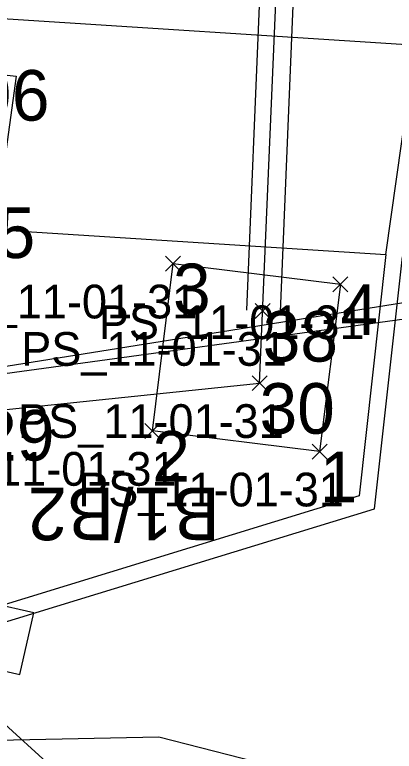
# Model space of a CAD drawing. Extents: x -728800 to -728100, y -1073200 to -1072700.
# Drawn here: x -728498.52 to -728494.02, y -1073052.38 to -1073043.64 of the extents above; entities that cross this region are included whole.
import ezdxf

# ---------------------------------------------------------------- set-up
doc = ezdxf.new("R2010")
doc.units = 0
for name, color, linetype in [('A1_OBVOD Spravy železnic', 7, 'Continuous'), ('A2_OBVOD STAVBY', 7, 'Continuous'), ('B1_body_poloha', 7, 'Continuous'), ('B2_body_číslo', 7, 'Continuous'), ('B3_body_popiska', 7, 'Continuous'), ('B4_Bodové pole', 7, 'Continuous'), ('B6_JŽM', 7, 'Continuous'), ('KOS_kabelová trasa', 7, 'Continuous'), ('KOS_nové prvky PZZ', 7, 'Continuous'), ('KTA_členění PS a SO', 7, 'Continuous'), ('ZA_02_Dočasný_do_1_roku', 7, 'Continuous')]:
    doc.layers.add(name, color=color, linetype=linetype)

msp = doc.modelspace()

# ---------------------------------------------------------------- linework, layer by layer
at = {"layer": 'A1_OBVOD Spravy železnic'}
msp.add_lwpolyline([(-728503.24, -1073052.34), (-728496.81, -1073052.21), (-728491.97, -1073053.44), (-728477.97, -1073053.19), (-728470.97, -1073054.08), (-728434.43, -1073049.27), (-728361.73, -1073039.5), (-728349.1656, -1073038.9844)], dxfattribs=at)
at = {"layer": 'A2_OBVOD STAVBY'}
msp.add_lwpolyline([(-728503.756, -1073049.5471), (-728504.3576, -1073053.4259), (-728503.4626, -1073053.5721), (-728499.6278, -1073054.1986), (-728499.1285, -1073052.28), (-728499.1998, -1073051.021), (-728494.2501, -1073049.503), (-728493.9181, -1073046.5148)], dxfattribs=at)
at = {"layer": 'B1_body_poloha'}
for p, q in [((-728496.7304, -1073046.5076), (-728496.5536, -1073046.6844)), ((-728496.7304, -1073046.6844), (-728496.5536, -1073046.5076)), ((-728494.7454, -1073046.7536), (-728494.5686, -1073046.9304)), ((-728494.7454, -1073046.9304), (-728494.5686, -1073046.7536)), ((-728495.6664, -1073047.0696), (-728495.4896, -1073047.2464)), ((-728495.6664, -1073047.2464), (-728495.4896, -1073047.0696)), ((-728495.7034, -1073047.9256), (-728495.5266, -1073048.1024)), ((-728495.7034, -1073048.1024), (-728495.5266, -1073047.9256)), ((-728496.9754, -1073048.4926), (-728496.7986, -1073048.6694)), ((-728496.9754, -1073048.6694), (-728496.7986, -1073048.4926)), ((-728494.9904, -1073048.7376), (-728494.8136, -1073048.9144)), ((-728494.9904, -1073048.9144), (-728494.8136, -1073048.7376))]:
    msp.add_line(p, q, dxfattribs=at)
at = {"layer": 'B2_body_číslo'}
for p, q in [((-728496.642, -1073046.596), (-728496.642, -1073046.596)), ((-728494.657, -1073046.842), (-728494.657, -1073046.842)), ((-728495.578, -1073047.158), (-728495.578, -1073047.158)), ((-728495.615, -1073048.014), (-728495.615, -1073048.014)), ((-728496.887, -1073048.581), (-728496.887, -1073048.581)), ((-728494.902, -1073048.826), (-728494.902, -1073048.826))]:
    msp.add_line(p, q, dxfattribs=at)
at = {"layer": 'B4_Bodové pole'}
msp.add_line((-728502.086, -1073048.369), (-728399.517, -1073034.362), dxfattribs=at)
msp.add_lwpolyline([(-728665.963, -1072915.444), (-728594.709, -1073015.734), (-728502.086, -1073048.369), (-728347.458, -1073023.537)], dxfattribs=at)
at = {"layer": 'B6_JŽM'}
for points in [[(-728300.8085, -1073024.3545), (-728320.8, -1073026.914), (-728374.008, -1073033.722), (-728429.095, -1073040.747), (-728461.932, -1073044.273), (-728481.199, -1073044.815), (-728499.353, -1073043.648), (-728506.01, -1073042.737), (-728514.574, -1073041.329), (-728535.848, -1073035.998), (-728561.353, -1073026.113), (-728583.963, -1073013.524), (-728603.757, -1072998.891), (-728619.185, -1072984.418), (-728634.193, -1072966.825), (-728646.078, -1072949.194), (-728656.182, -1072930.072), (-728664.987, -1072910.227), (-728668.627, -1072901.808), (-728681.252, -1072876.016), (-728691.886, -1072859.663)], [(-728499.357, -1073052.035), (-728499.1918, -1073051.3034), (-728498.4602, -1073051.4687), (-728498.295, -1073050.7371), (-728499.7581, -1073050.4066), (-728499.9233, -1073051.1382), (-728499.1918, -1073051.3034)]]:
    msp.add_lwpolyline(points, dxfattribs=at)
at = {"layer": 'KOS_kabelová trasa'}
for p, q in [((-728495.7665, -1073047.15), (-728495.3938, -1073038.2172)), ((-728495.3669, -1073047.1667), (-728494.9941, -1073038.2339))]:
    msp.add_line(p, q, dxfattribs=at)
msp.add_lwpolyline([(-728499.6877, -1073048.4364), (-728495.6152, -1073048.0137), (-728495.1842, -1073037.964)], dxfattribs=at)
msp.add_lwpolyline([(-728494.9024, -1073048.8265), (-728496.8873, -1073048.581), (-728496.6418, -1073046.5961), (-728494.6569, -1073046.8416)], close=True, dxfattribs=at)
at = {"layer": 'KTA_členění PS a SO'}
msp.add_line((-728495.2832, -1073055.0939), (-728501.1855, -1073049.7553), dxfattribs=at)
at = {"layer": 'ZA_02_Dočasný_do_1_roku'}
for points in [[(-728501.19, -1073037.94), (-728502.0422, -1073043.9717), (-728498.5021, -1073044.3719), (-728498.7556, -1073046.1916), (-728494.1165, -1073046.4898), (-728493.3495, -1073041.0682)], [(-728502.83, -1073049.48), (-728502.0422, -1073043.9717), (-728498.5021, -1073044.3719), (-728498.7556, -1073046.1916), (-728494.1165, -1073046.4898), (-728494.4344, -1073049.3504), (-728499.4083, -1073050.8758), (-728499.33, -1073052.26)]]:
    msp.add_lwpolyline(points, dxfattribs=at)

# ---------------------------------------------------------------- texts
at = {"layer": 'B2_body_číslo'}
for s, p in [('96', (-728499, -1073044.9)), ('95', (-728499.17, -1073046.53)), ('3', (-728496.642, -1073047.196)), ('4', (-728494.657, -1073047.442)), ('38', (-728495.578, -1073047.758)), ('30', (-728495.615, -1073048.614)), ('29', (-728498.9404, -1073048.9325)), ('2', (-728496.887, -1073049.181)), ('1', (-728494.902, -1073049.426))]:
    msp.add_text(s, height=0.6, dxfattribs=at).set_placement(p)
at = {"layer": 'B3_body_popiska'}
for p in [(-728499.507, -1073047.246), (-728497.522, -1073047.492), (-728498.443, -1073047.808), (-728498.48, -1073048.664), (-728499.752, -1073049.231), (-728497.767, -1073049.476)]:
    msp.add_text('PS_11-01-31', height=0.4, dxfattribs=at).set_placement(p)
at = {"layer": 'KOS_nové prvky PZZ'}
msp.add_text('B1/B2', height=0.625, rotation=180, dxfattribs=at).set_placement((-728496.0881, -1073049.2521))

doc.saveas('drawing.dxf')
